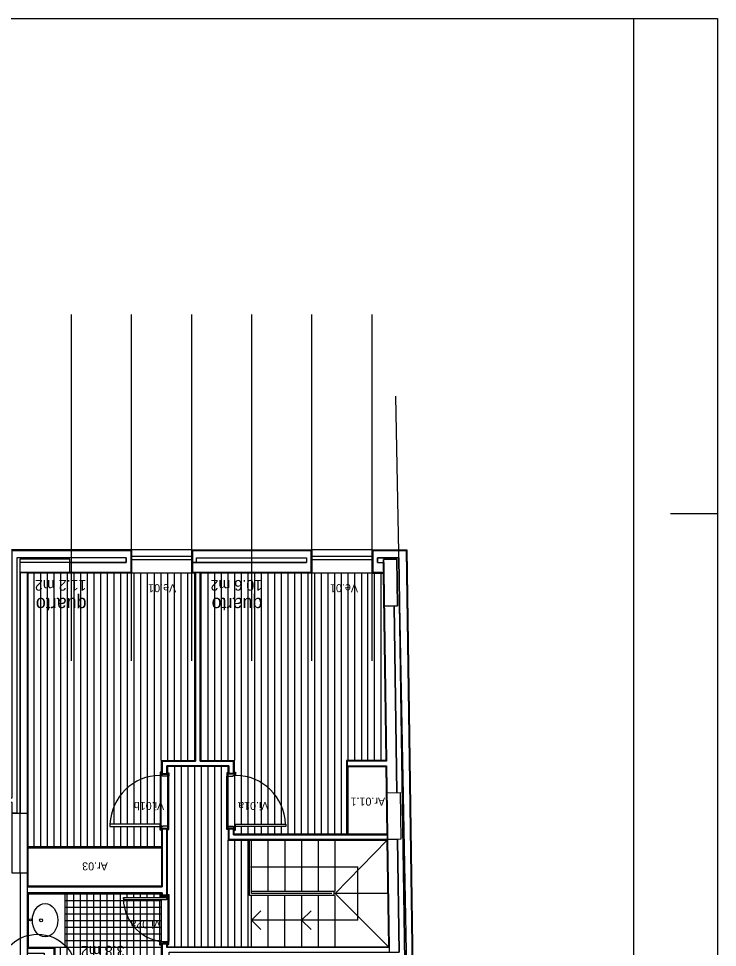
# Model space of a CAD drawing. Extents: x 1278 to 1356, y -253.7 to -224.
# Drawn here: x 1345.5 to 1355.97, y -237.88 to -223.96 of the extents above; entities that cross this region are included whole.
import ezdxf

# ---------------------------------------------------------------- set-up
doc = ezdxf.new("R2010")
doc.units = 0
for name, color, linetype in [('Level 1', 7, 'Continuous'), ('Level 10', 7, 'Continuous'), ('Level 11', 7, 'Continuous'), ('Level 13', 7, 'Continuous'), ('Level 2', 7, 'Continuous'), ('Level 25', 7, 'Continuous'), ('Level 4', 7, 'Continuous'), ('Level 40', 7, 'Continuous'), ('Level 60', 7, 'Continuous'), ('Level 62', 7, 'Continuous'), ('Level 65', 7, 'Continuous'), ('Level 66', 7, 'Continuous'), ('Level 67', 7, 'Continuous'), ('Level 69', 7, 'Continuous'), ('Level 70', 7, 'Continuous'), ('Level 93', 7, 'Continuous')]:
    doc.layers.add(name, color=color, linetype=linetype)

msp = doc.modelspace()

# ---------------------------------------------------------------- linework, layer by layer
at = {"layer": 'Level 1'}
for p, q in [((1347.184, -231.934), (1345.404, -231.934)), ((1347.184, -231.934), (1347.184, -232.264)), ((1348.104, -231.934), (1349.884, -231.934)), ((1348.104, -232.264), (1348.104, -231.934)), ((1349.884, -231.934), (1349.884, -232.264)), ((1351.306, -231.934), (1350.804, -231.934)), ((1350.804, -231.934), (1350.804, -232.264)), ((1347.114, -232.044), (1345.474, -232.044)), ((1347.114, -232.044), (1347.114, -232.114)), ((1348.164, -232.114), (1348.164, -232.044)), ((1349.814, -232.044), (1349.814, -232.114)), ((1350.874, -232.114), (1350.874, -232.044)), ((1347.114, -232.114), (1345.524, -232.114)), ((1347.184, -232.264), (1345.524, -232.264)), ((1349.884, -232.264), (1348.104, -232.264)), ((1348.149, -235.089), (1348.149, -232.264)), ((1348.219, -232.264), (1348.219, -235.089)), ((1350.804, -232.264), (1350.971, -232.264)), ((1350.971, -232.264), (1351.011, -235.089)), ((1351.128, -232.765), (1351.167, -235.562)), ((1347.649, -235.089), (1348.149, -235.089)), ((1347.649, -235.274), (1347.649, -235.089)), ((1348.219, -235.089), (1348.721, -235.089)), ((1348.721, -235.089), (1348.721, -235.274)), ((1351.011, -235.089), (1350.421, -235.089)), ((1350.421, -235.089), (1350.421, -235.159)), ((1347.639, -235.274), (1347.729, -235.274)), ((1347.719, -235.159), (1347.719, -235.274)), ((1348.651, -235.159), (1347.724, -235.159)), ((1348.731, -235.274), (1348.641, -235.274)), ((1348.651, -235.274), (1348.651, -235.159)), ((1350.421, -235.159), (1351.012, -235.159)), ((1351.012, -235.159), (1351.026, -236.194)), ((1347.639, -236.104), (1347.729, -236.104)), ((1347.649, -236.104), (1347.649, -236.974)), ((1347.719, -237.099), (1347.719, -236.104)), ((1348.731, -236.104), (1348.641, -236.104)), ((1348.651, -236.104), (1348.651, -236.264)), ((1348.721, -236.194), (1348.721, -236.104)), ((1348.721, -236.194), (1351.027, -236.194)), ((1351.177, -236.262), (1351.201, -237.954)), ((1348.651, -236.264), (1351.027, -236.264)), ((1351.027, -236.264), (1351.051, -237.954)), ((1345.524, -236.771), (1345.524, -239.409)), ((1347.649, -236.974), (1345.634, -236.974)), ((1345.634, -237.064), (1347.649, -237.064)), ((1347.634, -237.099), (1347.729, -237.099)), ((1347.634, -237.829), (1347.729, -237.829)), ((1347.649, -237.829), (1347.649, -239.409)), ((1347.719, -237.884), (1347.719, -237.829))]:
    msp.add_line(p, q, dxfattribs=at)
at = {"layer": 'Level 10'}
for p, q in [((1345.734, -236.374), (1345.734, -232.274)), ((1345.834, -236.374), (1345.834, -232.274)), ((1345.934, -236.374), (1345.934, -232.274)), ((1346.034, -236.374), (1346.034, -232.274)), ((1346.134, -236.374), (1346.134, -232.274)), ((1346.234, -236.374), (1346.234, -232.274)), ((1346.334, -236.374), (1346.334, -232.274)), ((1346.434, -236.374), (1346.434, -232.274)), ((1346.534, -236.374), (1346.534, -232.274)), ((1346.634, -236.374), (1346.634, -232.274)), ((1346.734, -236.374), (1346.734, -232.274)), ((1346.834, -236.374), (1346.834, -232.274)), ((1346.934, -236.034), (1346.934, -232.274)), ((1347.034, -236.034), (1347.034, -232.274)), ((1347.134, -236.034), (1347.134, -232.274)), ((1347.234, -236.034), (1347.234, -232.274)), ((1347.334, -236.034), (1347.334, -232.274)), ((1347.434, -236.034), (1347.434, -232.274)), ((1347.534, -236.034), (1347.534, -232.274)), ((1347.634, -235.074), (1347.634, -232.274)), ((1347.734, -235.074), (1347.734, -232.274)), ((1347.834, -235.074), (1347.834, -232.274)), ((1347.934, -235.074), (1347.934, -232.274)), ((1348.034, -235.074), (1348.034, -232.274)), ((1348.334, -232.274), (1348.334, -235.074)), ((1348.434, -232.274), (1348.434, -235.074)), ((1348.534, -232.274), (1348.534, -235.074)), ((1348.634, -232.274), (1348.634, -235.074)), ((1348.734, -232.274), (1348.734, -235.074)), ((1348.834, -232.274), (1348.834, -236.034)), ((1348.934, -232.274), (1348.934, -236.034)), ((1349.034, -232.274), (1349.034, -236.034)), ((1349.134, -232.274), (1349.134, -236.034)), ((1349.234, -232.274), (1349.234, -236.034)), ((1349.334, -232.274), (1349.334, -236.034)), ((1349.434, -232.274), (1349.434, -236.034)), ((1349.534, -232.274), (1349.534, -236.184)), ((1349.634, -232.274), (1349.634, -236.184)), ((1349.734, -232.274), (1349.734, -236.184)), ((1349.834, -232.274), (1349.834, -236.184)), ((1349.934, -232.274), (1349.934, -236.184)), ((1350.034, -232.274), (1350.034, -236.184)), ((1350.134, -232.274), (1350.134, -236.184)), ((1350.234, -232.274), (1350.234, -236.184)), ((1350.334, -232.274), (1350.334, -236.184)), ((1350.434, -232.274), (1350.434, -235.079)), ((1350.534, -232.274), (1350.534, -235.079)), ((1350.634, -232.274), (1350.634, -235.079)), ((1350.725, -232.274), (1350.725, -235.079)), ((1350.825, -232.274), (1350.825, -235.079)), ((1350.925, -232.274), (1350.925, -235.079)), ((1347.634, -236.074), (1347.634, -235.274)), ((1347.734, -236.074), (1347.734, -235.274)), ((1347.836, -235.174), (1347.836, -237.874)), ((1347.936, -235.174), (1347.936, -237.874)), ((1348.036, -235.174), (1348.036, -237.874)), ((1348.136, -235.174), (1348.136, -237.874)), ((1348.236, -235.174), (1348.236, -237.874)), ((1348.336, -235.174), (1348.336, -237.874)), ((1348.436, -235.174), (1348.436, -237.874)), ((1348.536, -235.174), (1348.536, -237.874)), ((1348.636, -235.274), (1348.636, -236.074)), ((1348.736, -235.274), (1348.736, -236.054)), ((1346.934, -236.374), (1346.934, -236.069)), ((1347.034, -236.374), (1347.034, -236.069)), ((1347.134, -236.374), (1347.134, -236.069)), ((1347.234, -236.374), (1347.234, -236.069)), ((1347.334, -236.374), (1347.334, -236.069)), ((1347.434, -236.374), (1347.434, -236.069)), ((1347.534, -236.374), (1347.534, -236.069)), ((1348.834, -236.069), (1348.834, -236.184)), ((1348.934, -236.069), (1348.934, -236.184)), ((1349.034, -236.069), (1349.034, -236.184)), ((1349.134, -236.069), (1349.134, -236.184)), ((1349.234, -236.069), (1349.234, -236.184)), ((1349.334, -236.069), (1349.334, -236.184)), ((1349.434, -236.069), (1349.434, -236.184)), ((1348.636, -236.274), (1348.636, -237.874)), ((1348.736, -236.274), (1348.736, -237.874)), ((1348.836, -236.274), (1348.836, -237.874)), ((1348.936, -236.274), (1348.936, -237.874)), ((1346.229, -238.113), (1346.229, -237.079)), ((1346.329, -238.1), (1346.329, -237.079)), ((1346.429, -238.099), (1346.429, -237.079)), ((1346.529, -238.149), (1346.529, -237.079)), ((1346.629, -238.624), (1346.629, -237.079)), ((1346.729, -238.624), (1346.729, -237.079)), ((1346.829, -238.624), (1346.829, -237.079)), ((1346.929, -238.624), (1346.929, -237.079)), ((1347.029, -238.624), (1347.029, -237.079)), ((1347.129, -237.134), (1347.129, -237.079)), ((1347.229, -237.134), (1347.229, -237.079)), ((1347.329, -237.134), (1347.329, -237.079)), ((1347.429, -237.134), (1347.429, -237.079)), ((1347.529, -237.134), (1347.529, -237.079)), ((1346.199, -237.179), (1347.634, -237.179)), ((1347.129, -238.179), (1347.129, -237.169)), ((1347.229, -238.108), (1347.229, -237.169)), ((1347.329, -238.103), (1347.329, -237.169)), ((1347.429, -238.113), (1347.429, -237.169)), ((1347.529, -238.13), (1347.529, -237.169)), ((1347.634, -237.169), (1347.634, -237.799)), ((1347.734, -237.124), (1347.734, -237.799)), ((1346.199, -237.279), (1347.634, -237.279)), ((1346.199, -237.379), (1347.634, -237.379)), ((1346.199, -237.479), (1347.634, -237.479)), ((1346.199, -237.579), (1347.634, -237.579)), ((1346.199, -237.679), (1347.634, -237.679)), ((1346.199, -237.779), (1347.634, -237.779)), ((1346.129, -238.129), (1346.129, -237.879)), ((1346.199, -237.879), (1347.634, -237.879))]:
    msp.add_line(p, q, dxfattribs=at)
at = {"layer": 'Level 11'}
for centre, radius in [((1345.677, -237.468), 0.0159), ((1345.838, -237.475), 0.0225)]:
    msp.add_circle(centre, radius, dxfattribs=at)
msp.add_ellipse((1345.898, -237.475), major_axis=(0, 0.25), ratio=0.76, dxfattribs=at)
at = {"layer": 'Level 13'}
for p, q in [((1347.619, -235.254), (1347.619, -235.304)), ((1347.629, -235.254), (1347.619, -235.254)), ((1347.629, -235.259), (1347.629, -235.254)), ((1347.634, -235.259), (1347.629, -235.259)), ((1347.634, -235.304), (1347.634, -235.259)), ((1347.634, -235.284), (1347.734, -235.284)), ((1347.634, -235.304), (1347.634, -235.284)), ((1347.734, -235.314), (1347.734, -235.269)), ((1347.734, -235.269), (1347.739, -235.269)), ((1347.734, -235.284), (1347.734, -235.314)), ((1347.739, -235.269), (1347.739, -235.264)), ((1347.739, -235.264), (1347.749, -235.264)), ((1347.749, -235.264), (1347.749, -235.314)), ((1348.621, -235.264), (1348.621, -235.314)), ((1348.631, -235.264), (1348.621, -235.264)), ((1348.631, -235.269), (1348.631, -235.264)), ((1348.636, -235.269), (1348.631, -235.269)), ((1348.636, -235.314), (1348.636, -235.269)), ((1348.736, -235.284), (1348.636, -235.284)), ((1348.636, -235.284), (1348.636, -235.314)), ((1348.736, -235.304), (1348.736, -235.259)), ((1348.736, -235.259), (1348.741, -235.259)), ((1348.736, -235.304), (1348.736, -235.284)), ((1348.741, -235.259), (1348.741, -235.254)), ((1348.741, -235.254), (1348.751, -235.254)), ((1348.751, -235.254), (1348.751, -235.304)), ((1350.411, -235.169), (1350.411, -236.184)), ((1350.431, -235.169), (1350.431, -236.184)), ((1347.619, -235.304), (1347.634, -235.304)), ((1347.654, -235.304), (1347.634, -235.304)), ((1347.654, -235.314), (1347.654, -235.304)), ((1347.734, -235.314), (1347.654, -235.314)), ((1347.749, -235.314), (1347.734, -235.314)), ((1348.621, -235.314), (1348.636, -235.314)), ((1348.636, -235.314), (1348.716, -235.314)), ((1348.716, -235.314), (1348.716, -235.304)), ((1348.716, -235.304), (1348.736, -235.304)), ((1348.751, -235.304), (1348.736, -235.304)), ((1347.619, -236.034), (1346.869, -236.034)), ((1346.869, -236.034), (1346.869, -236.069)), ((1346.869, -236.069), (1347.619, -236.069)), ((1347.619, -236.069), (1347.619, -236.034)), ((1347.619, -236.124), (1347.619, -236.074)), ((1347.619, -236.074), (1347.634, -236.074)), ((1347.634, -236.119), (1347.629, -236.119)), ((1347.629, -236.119), (1347.629, -236.124)), ((1347.634, -236.054), (1347.634, -236.074)), ((1347.654, -236.074), (1347.634, -236.074)), ((1347.634, -236.074), (1347.634, -236.094)), ((1347.634, -236.074), (1347.634, -236.119)), ((1347.634, -236.094), (1347.734, -236.094)), ((1347.734, -236.064), (1347.654, -236.064)), ((1347.654, -236.064), (1347.654, -236.074)), ((1347.734, -236.094), (1347.734, -236.064)), ((1347.749, -236.064), (1347.734, -236.064)), ((1347.734, -236.064), (1347.734, -236.109)), ((1347.734, -236.109), (1347.739, -236.109)), ((1347.739, -236.109), (1347.739, -236.114)), ((1347.739, -236.114), (1347.749, -236.114)), ((1347.749, -236.114), (1347.749, -236.064)), ((1348.621, -236.114), (1348.621, -236.064)), ((1348.621, -236.064), (1348.636, -236.064)), ((1348.631, -236.114), (1348.621, -236.114)), ((1348.636, -236.109), (1348.631, -236.109)), ((1348.631, -236.109), (1348.631, -236.114)), ((1348.636, -236.094), (1348.636, -236.064)), ((1348.636, -236.064), (1348.716, -236.064)), ((1348.636, -236.064), (1348.636, -236.109)), ((1348.736, -236.094), (1348.636, -236.094)), ((1348.716, -236.064), (1348.716, -236.074)), ((1348.716, -236.074), (1348.736, -236.074)), ((1348.736, -236.054), (1348.736, -236.074)), ((1348.736, -236.074), (1348.736, -236.094)), ((1348.751, -236.074), (1348.736, -236.074)), ((1348.736, -236.074), (1348.736, -236.119)), ((1348.736, -236.119), (1348.741, -236.119)), ((1348.741, -236.119), (1348.741, -236.124)), ((1348.751, -236.069), (1348.751, -236.034)), ((1348.751, -236.034), (1349.501, -236.034)), ((1349.501, -236.069), (1348.751, -236.069)), ((1348.751, -236.124), (1348.751, -236.074)), ((1349.501, -236.034), (1349.501, -236.069)), ((1347.629, -236.124), (1347.619, -236.124)), ((1348.741, -236.124), (1348.751, -236.124)), ((1347.634, -236.374), (1345.634, -236.374)), ((1347.634, -236.374), (1345.634, -236.374)), ((1347.634, -236.394), (1345.634, -236.394)), ((1347.629, -237.079), (1347.614, -237.079)), ((1347.614, -237.079), (1347.614, -237.129)), ((1347.629, -237.129), (1347.629, -237.079)), ((1347.734, -237.139), (1347.734, -237.089)), ((1347.734, -237.089), (1347.749, -237.089)), ((1347.749, -237.089), (1347.749, -237.139)), ((1347.07, -237.134), (1347.725, -237.134)), ((1347.07, -237.154), (1347.07, -237.134)), ((1347.08, -237.154), (1347.07, -237.154)), ((1347.08, -237.169), (1347.08, -237.154)), ((1347.715, -237.169), (1347.08, -237.169)), ((1347.614, -237.129), (1347.629, -237.129)), ((1347.629, -237.129), (1347.629, -237.109)), ((1347.629, -237.109), (1347.734, -237.109)), ((1347.734, -237.129), (1347.629, -237.129)), ((1347.715, -237.154), (1347.715, -237.169)), ((1347.725, -237.154), (1347.715, -237.154)), ((1347.725, -237.134), (1347.725, -237.154)), ((1347.734, -237.109), (1347.734, -237.139)), ((1347.749, -237.139), (1347.734, -237.139)), ((1347.749, -237.789), (1347.734, -237.789)), ((1347.734, -237.819), (1347.734, -237.789)), ((1347.734, -237.789), (1347.734, -237.839)), ((1347.749, -237.839), (1347.749, -237.789)), ((1347.614, -237.849), (1347.614, -237.799)), ((1347.614, -237.799), (1347.629, -237.799)), ((1347.629, -237.849), (1347.614, -237.849)), ((1347.734, -237.799), (1347.629, -237.799)), ((1347.629, -237.799), (1347.629, -237.819)), ((1347.629, -237.799), (1347.629, -237.849)), ((1347.629, -237.819), (1347.734, -237.819)), ((1347.734, -237.839), (1347.749, -237.839))]:
    msp.add_line(p, q, dxfattribs=at)
at = {"layer": 'Level 2'}
for p, q in [((1348.094, -231.924), (1347.194, -231.924)), ((1350.794, -231.924), (1349.894, -231.924)), ((1348.094, -232.024), (1347.194, -232.024)), ((1348.094, -232.074), (1347.194, -232.074)), ((1350.794, -232.024), (1349.894, -232.024)), ((1350.794, -232.074), (1349.894, -232.074)), ((1348.094, -232.274), (1347.194, -232.274)), ((1350.794, -232.274), (1349.894, -232.274)), ((1348.96, -237.104), (1348.96, -236.274)), ((1348.99, -237.074), (1348.99, -236.274)), ((1349.241, -237.044), (1349.241, -236.274)), ((1349.491, -237.044), (1349.491, -236.274)), ((1349.741, -237.044), (1349.741, -236.274)), ((1349.991, -237.044), (1349.991, -236.274)), ((1350.241, -237.044), (1350.241, -236.274)), ((1350.241, -237.074), (1351.019, -236.274)), ((1348.976, -236.674), (1350.582, -236.674)), ((1350.582, -237.474), (1350.582, -236.674)), ((1345.651, -237.081), (1346.199, -237.081)), ((1346.199, -237.879), (1346.199, -237.081)), ((1350.226, -237.044), (1348.99, -237.044)), ((1350.193, -237.074), (1348.99, -237.074)), ((1350.226, -237.104), (1350.226, -237.044)), ((1351.028, -237.074), (1350.226, -237.074)), ((1350.241, -237.074), (1351.039, -237.874)), ((1350.226, -237.104), (1348.96, -237.104)), ((1348.99, -237.874), (1348.99, -237.104)), ((1349.24, -237.874), (1349.24, -237.104)), ((1349.49, -237.874), (1349.49, -237.104)), ((1349.74, -237.104), (1349.74, -237.874)), ((1349.991, -237.874), (1349.991, -237.104)), ((1350.241, -237.874), (1350.241, -237.104)), ((1349.131, -237.333), (1348.99, -237.474)), ((1349.881, -237.333), (1349.74, -237.474)), ((1350.582, -237.474), (1348.99, -237.474)), ((1349.131, -237.615), (1348.99, -237.474)), ((1350.582, -237.474), (1349.726, -237.474)), ((1349.881, -237.615), (1349.74, -237.474)), ((1345.651, -237.879), (1346.199, -237.879))]:
    msp.add_line(p, q, dxfattribs=at)
at = {"layer": 'Level 25'}
msp.add_lwpolyline([(1351.178, -232.764), (1350.978, -232.767), (1350.967, -232.067), (1351.168, -232.064), (1351.178, -232.764)], dxfattribs=at)
msp.add_lwpolyline([(1351.226, -236.261), (1351.026, -236.264), (1351.016, -235.564), (1351.217, -235.561)], close=True, dxfattribs=at)
at = {"layer": 'Level 4'}
for p, q in [((1347.619, -235.304), (1347.619, -236.034)), ((1347.749, -236.064), (1347.749, -235.314)), ((1348.621, -236.064), (1348.621, -235.314)), ((1347.614, -237.799), (1347.614, -237.169)), ((1347.749, -237.139), (1347.749, -237.789))]:
    msp.add_line(p, q, dxfattribs=at)
for centre, major_axis, ratio, start_param, end_param in [((1347.619, -236.067), (0, -0.763), 0.982661, 3.141593, 4.668897), ((1348.751, -236.067), (0, -0.763), 0.982661, 1.614288, 3.141593), ((1347.725, -237.14), (0, 0.659), 0.994279, 1.591512, 3.141593)]:
    msp.add_ellipse(centre, major_axis=major_axis, ratio=ratio, start_param=start_param, end_param=end_param, dxfattribs=at)
at = {"layer": 'Level 62'}
for p, q in [((1354.716, -253.659), (1354.716, -223.959)), ((1355.966, -231.384), (1355.266, -231.384))]:
    msp.add_line(p, q, dxfattribs=at)
msp.add_lwpolyline([(1355.966, -223.959), (1355.966, -253.659), (1278.016, -253.659), (1278.016, -223.959)], close=True, dxfattribs=at)
at = {"layer": 'Level 65'}
for p, q in [((1347.194, -231.924), (1345.394, -231.924)), ((1347.194, -231.924), (1347.194, -232.274)), ((1348.094, -232.274), (1348.094, -231.924)), ((1348.094, -231.924), (1349.894, -231.924)), ((1349.894, -231.924), (1349.894, -232.274)), ((1350.794, -231.924), (1351.316, -231.924)), ((1350.794, -232.274), (1350.794, -231.924)), ((1351.316, -231.924), (1351.406, -238.206)), ((1351.168, -232.064), (1351.178, -232.764)), ((1351.168, -232.064), (1351.178, -232.764)), ((1347.194, -232.274), (1345.644, -232.274)), ((1345.644, -236.964), (1345.644, -232.274)), ((1348.139, -232.274), (1348.094, -232.274)), ((1348.139, -235.079), (1348.139, -232.274)), ((1348.229, -232.274), (1348.229, -235.079)), ((1349.894, -232.274), (1348.229, -232.274)), ((1350.794, -232.274), (1350.961, -232.274)), ((1350.961, -232.274), (1351, -235.079)), ((1347.639, -235.274), (1347.639, -235.079)), ((1347.639, -235.079), (1348.139, -235.079)), ((1348.229, -235.079), (1348.731, -235.079)), ((1348.731, -235.079), (1348.731, -235.274)), ((1351, -235.079), (1350.411, -235.079)), ((1350.411, -235.079), (1350.411, -235.169)), ((1347.729, -235.169), (1347.729, -235.274)), ((1348.641, -235.169), (1347.729, -235.169)), ((1348.641, -235.274), (1348.641, -235.169)), ((1350.411, -235.169), (1351.002, -235.169)), ((1351.002, -235.169), (1351.016, -236.184)), ((1347.639, -236.104), (1347.639, -236.964)), ((1347.729, -237.099), (1347.729, -236.104)), ((1348.641, -236.104), (1348.641, -236.274)), ((1348.731, -236.184), (1348.731, -236.104)), ((1351.016, -236.184), (1348.731, -236.184)), ((1348.641, -236.274), (1351.017, -236.274)), ((1351.017, -236.274), (1351.039, -237.874)), ((1347.639, -236.964), (1345.644, -236.964)), ((1345.649, -237.079), (1347.634, -237.079)), ((1345.649, -237.881), (1345.649, -237.079)), ((1347.634, -237.079), (1347.634, -237.099)), ((1346.049, -237.881), (1345.649, -237.881)), ((1346.049, -239.324), (1346.049, -237.881)), ((1347.634, -237.829), (1347.634, -239.324)), ((1347.729, -237.874), (1347.729, -237.829)), ((1347.729, -237.874), (1351.039, -237.874))]:
    msp.add_line(p, q, dxfattribs=at)
at = {"layer": 'Level 66'}
for p, q in [((1351.306, -231.934), (1351.396, -238.196)), ((1346.268, -232.064), (1345.518, -232.064)), ((1346.268, -232.114), (1346.268, -232.064)), ((1348.164, -232.044), (1349.814, -232.044)), ((1350.874, -232.044), (1351.197, -232.044)), ((1351.197, -232.044), (1351.284, -238.086)), ((1348.164, -232.114), (1349.814, -232.114)), ((1350.874, -232.114), (1350.972, -232.114)), ((1345.524, -236.771), (1345.524, -232.264)), ((1345.634, -239.409), (1345.634, -232.264)), ((1347.649, -235.159), (1347.649, -235.239)), ((1347.724, -235.159), (1347.719, -235.159)), ((1347.719, -235.159), (1347.719, -235.239)), ((1347.649, -237.064), (1347.649, -237.099))]:
    msp.add_line(p, q, dxfattribs=at)
for points in [[(1346.268, -232.064), (1345.518, -232.064), (1345.518, -232.264), (1346.268, -232.264)], [(1351.178, -232.764), (1351.168, -232.064), (1350.967, -232.067), (1350.978, -232.767)], [(1351.027, -236.264), (1351.016, -235.564), (1351.217, -235.561), (1351.227, -236.261)], [(1345.634, -236.771), (1345.404, -236.771), (1345.404, -235.871), (1345.634, -235.871)]]:
    msp.add_lwpolyline(points, close=True, dxfattribs=at)
at = {"layer": 'Level 67'}
for points in [[(1346.268, -232.264), (1346.268, -232.114), (1347.114, -232.114), (1347.114, -232.044), (1345.474, -232.044), (1345.474, -235.871), (1345.404, -235.871), (1345.404, -235.711), (1344.804, -235.711), (1344.804, -235.641), (1345.404, -235.641), (1345.404, -231.934), (1347.184, -231.934), (1347.184, -232.264)], [(1349.884, -232.264), (1349.884, -231.934), (1348.104, -231.934), (1348.104, -232.114), (1348.164, -232.114), (1348.164, -232.044), (1349.814, -232.044), (1349.814, -232.114), (1348.104, -232.114), (1348.104, -232.264)], [(1351.396, -238.196), (1351.244, -238.196), (1351.244, -238.086), (1351.284, -238.086), (1351.197, -232.044), (1350.874, -232.044), (1350.874, -232.114), (1350.972, -232.114), (1350.971, -232.264), (1350.804, -232.264), (1350.804, -231.934), (1351.306, -231.934), (1351.396, -238.196)], [(1345.524, -235.871), (1345.634, -235.871), (1345.634, -232.264), (1345.524, -232.264)], [(1348.219, -232.264), (1348.149, -232.264), (1348.149, -235.089), (1347.649, -235.089), (1347.649, -235.274), (1347.719, -235.274), (1347.719, -235.159), (1348.651, -235.159), (1348.651, -235.274), (1348.721, -235.274), (1348.721, -235.089), (1348.219, -235.089)], [(1351.128, -232.765), (1350.978, -232.767), (1351.011, -235.089), (1350.421, -235.089), (1350.421, -235.159), (1351.012, -235.159), (1351.017, -235.564), (1351.167, -235.562)], [(1347.719, -236.104), (1347.719, -237.099), (1347.649, -237.099), (1347.649, -237.064), (1345.634, -237.064), (1345.634, -236.974), (1347.649, -236.974), (1347.649, -236.11), (1347.649, -236.104)], [(1351.026, -236.194), (1351.026, -236.264), (1348.651, -236.264), (1348.651, -236.104), (1348.721, -236.104), (1348.721, -236.194), (1351.027, -236.194)], [(1345.634, -237.896), (1345.634, -237.966), (1345.884, -237.966), (1345.884, -239.339), (1345.634, -239.339), (1345.634, -239.409), (1347.754, -239.409), (1347.754, -238.034), (1347.754, -237.954), (1351.201, -237.954), (1351.177, -236.262), (1351.027, -236.264), (1351.05, -237.884), (1347.719, -237.884), (1347.719, -237.829), (1347.649, -237.829), (1347.649, -239.339), (1346.034, -239.339), (1346.034, -237.896)], [(1345.634, -236.771), (1345.524, -236.771), (1345.524, -239.409), (1345.634, -239.409), (1345.634, -236.771)]]:
    msp.add_lwpolyline(points, close=True, dxfattribs=at)
at = {"layer": 'Level 69'}
msp.add_circle((1345.787, -238.268), 0.584, dxfattribs=at)
at = {"layer": 'Level 70'}
msp.add_line((1351.148, -229.62), (1351.553, -250.792), dxfattribs=at)
at = {"layer": 'Level 93'}
for p, q in [((1346.294, -233.587), (1346.294, -228.394)), ((1347.194, -233.587), (1347.194, -228.394)), ((1348.094, -233.587), (1348.094, -228.394)), ((1348.994, -233.587), (1348.994, -228.394)), ((1349.894, -233.587), (1349.894, -228.394)), ((1350.794, -233.587), (1350.794, -228.394))]:
    msp.add_line(p, q, dxfattribs=at)

# ---------------------------------------------------------------- texts
at = {"layer": 'Level 40'}
for s, p in [('Ve.01', (1347.861, -232.437)), ('Ve.01', (1350.584, -232.437)), ('Vi.01b', (1347.681, -235.701)), ('Vi.01a', (1349.244, -235.701)), ('Ar.01.1', (1350.99, -235.636)), ('Ar.03', (1346.837, -236.607)), ('Vi.02a', (1347.63, -237.475))]:
    msp.add_text(s, height=0.12, rotation=180, dxfattribs=at).set_placement(p)
at = {"layer": 'Level 60'}
for s, height, p in [('11.2 m2', 0.16, (1346.518, -232.374)), ('10.6 m2', 0.16, (1349.149, -232.374)), ('quarto', 0.2, (1346.518, -232.642)), ('quarto', 0.2, (1349.151, -232.642)), ('3.8 m2', 0.16, (1347.088, -237.858))]:
    msp.add_text(s, height=height, rotation=180, dxfattribs=at).set_placement(p)

doc.saveas('drawing.dxf')
